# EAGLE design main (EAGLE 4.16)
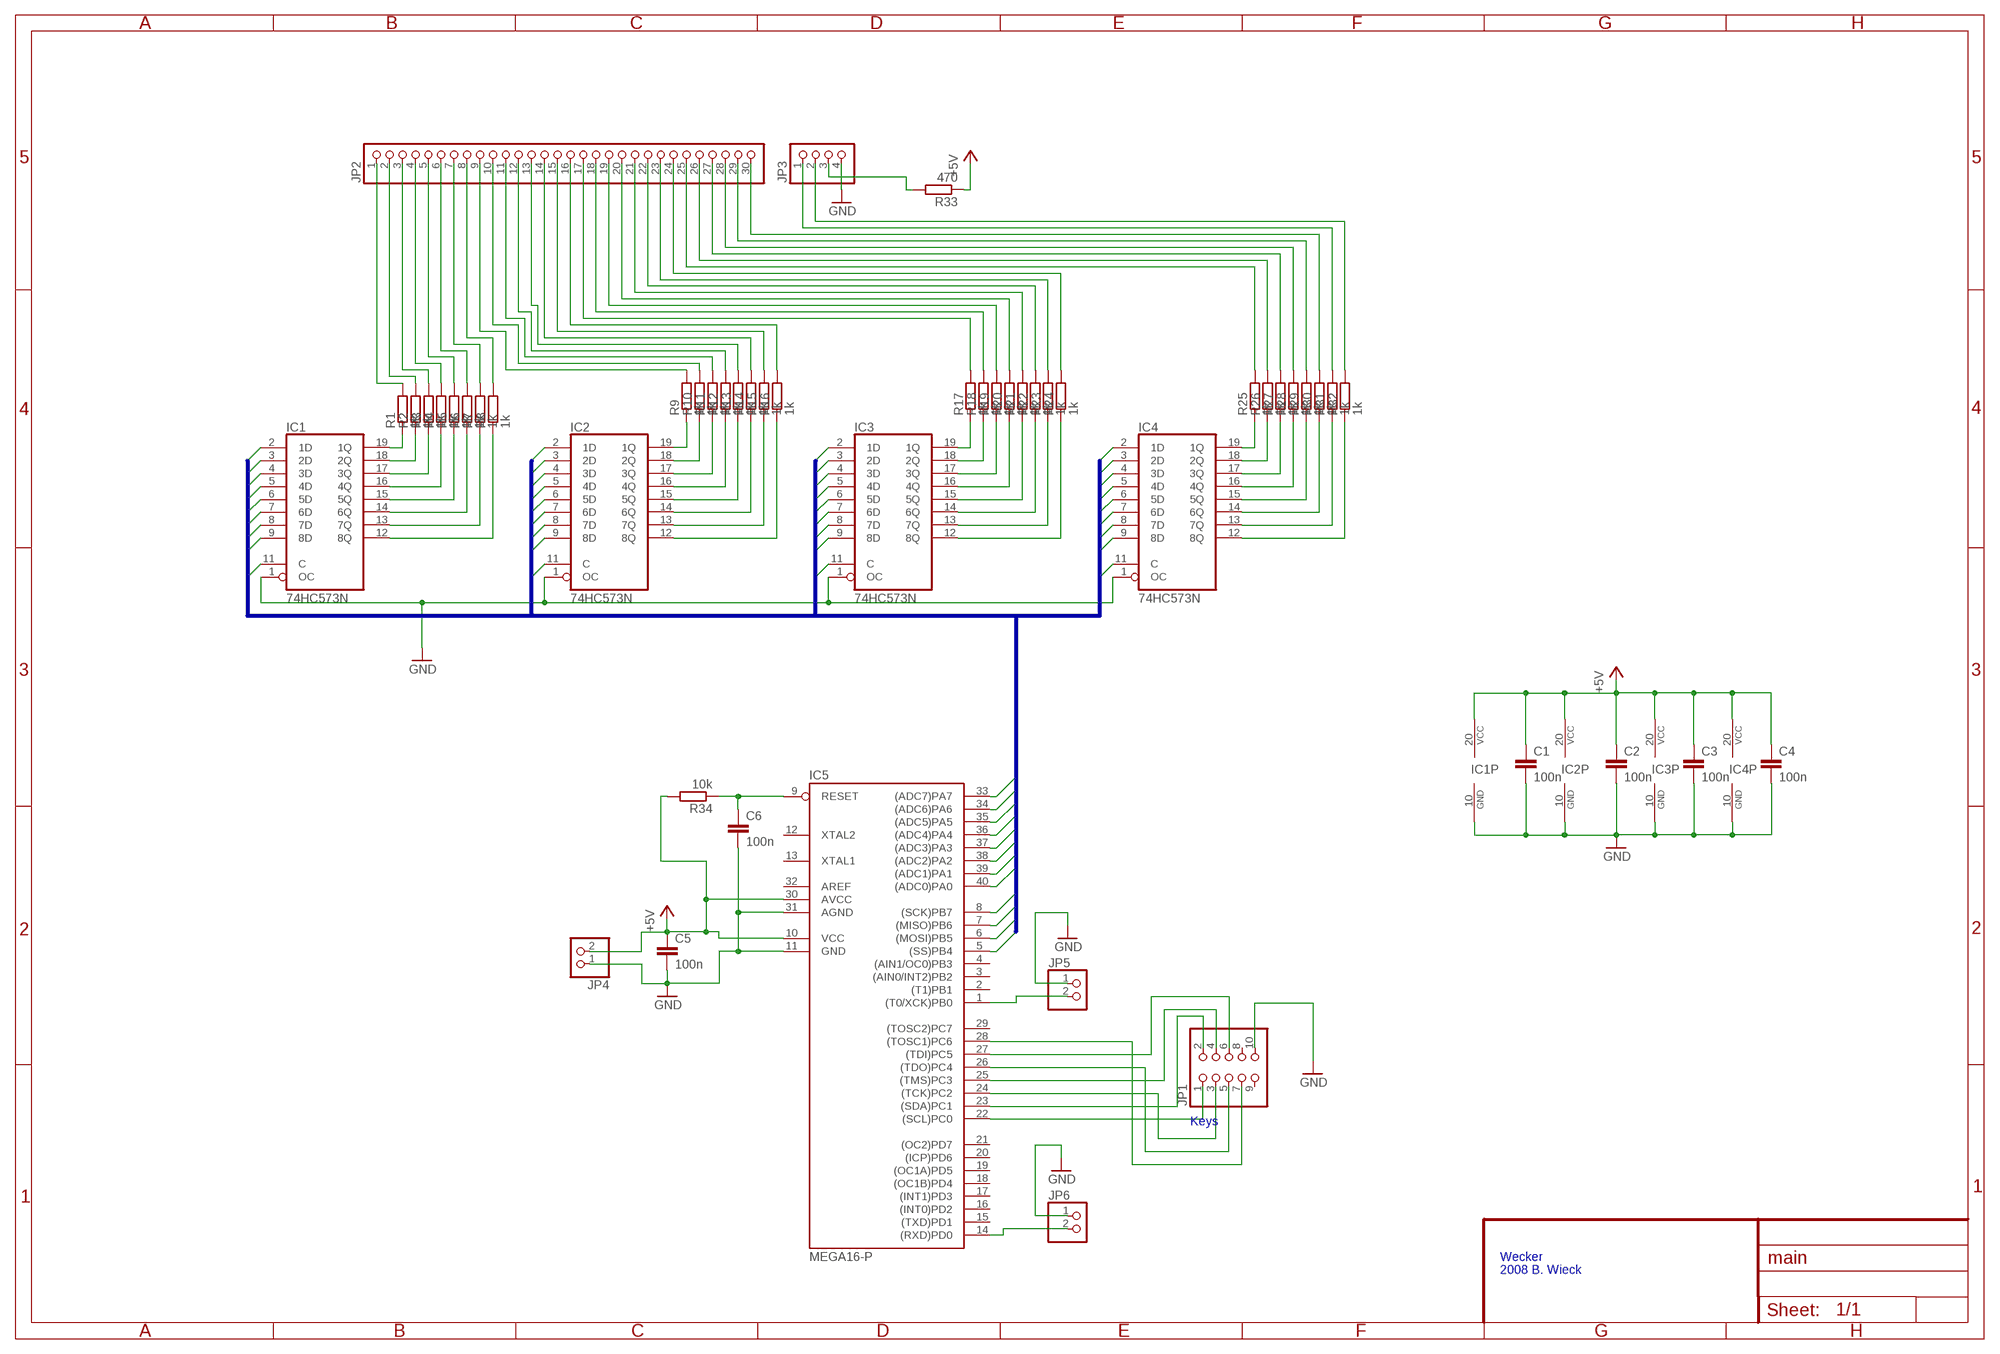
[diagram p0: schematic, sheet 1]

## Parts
C1  100n  C-EU050-024X044  [C050-024X044]
C2  100n  C-EU050-024X044  [C050-024X044]
C3  100n  C-EU050-024X044  [C050-024X044]
C4  100n  C-EU050-024X044  [C050-024X044]
C5  100n  C-EU050-024X044  [C050-024X044]
C6  100n  C-EU050-024X044  [C050-024X044]
IC1  74HC573N  [DIL20]
IC2  74HC573N  [DIL20]
IC3  74HC573N  [DIL20]
IC4  74HC573N  [DIL20]
IC5  MEGA16-P  [DIL40]
JP1  PINHD-2X5  [2X05]
JP2  PINHD-1X30  [1X30]
JP3  PINHD-1X4  [1X04]
JP4  PINHD-1X2  [1X02]
JP5  PINHD-1X2  [1X02]
JP6  PINHD-1X2  [1X02]
R1  1k  R-EU_0207/2V  [0207/2V]
R2  1k  R-EU_0207/2V  [0207/2V]
R3  1k  R-EU_0207/2V  [0207/2V]
R4  1k  R-EU_0207/2V  [0207/2V]
R5  1k  R-EU_0207/2V  [0207/2V]
R6  1k  R-EU_0207/2V  [0207/2V]
R7  1k  R-EU_0207/2V  [0207/2V]
R8  1k  R-EU_0207/2V  [0207/2V]
R9  1k  R-EU_0207/2V  [0207/2V]
R10  1k  R-EU_0207/2V  [0207/2V]
R11  1k  R-EU_0207/2V  [0207/2V]
R12  1k  R-EU_0207/2V  [0207/2V]
R13  1k  R-EU_0207/2V  [0207/2V]
R14  1k  R-EU_0207/2V  [0207/2V]
R15  1k  R-EU_0207/2V  [0207/2V]
R16  1k  R-EU_0207/2V  [0207/2V]
R17  1k  R-EU_0207/2V  [0207/2V]
R18  1k  R-EU_0207/2V  [0207/2V]
R19  1k  R-EU_0207/2V  [0207/2V]
R20  1k  R-EU_0207/2V  [0207/2V]
R21  1k  R-EU_0207/2V  [0207/2V]
R22  1k  R-EU_0207/2V  [0207/2V]
R23  1k  R-EU_0207/2V  [0207/2V]
R24  1k  R-EU_0207/2V  [0207/2V]
R25  1k  R-EU_0207/2V  [0207/2V]
R26  1k  R-EU_0207/2V  [0207/2V]
R27  1k  R-EU_0207/2V  [0207/2V]
R28  1k  R-EU_0207/2V  [0207/2V]
R29  1k  R-EU_0207/2V  [0207/2V]
R30  1k  R-EU_0207/2V  [0207/2V]
R31  1k  R-EU_0207/2V  [0207/2V]
R32  1k  R-EU_0207/2V  [0207/2V]
R33  470  R-EU_0207/2V  [0207/2V]
R34  10k  R-EU_0207/10  [0207/10]

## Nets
+5V: C1.1 C2.1 C3.1 C4.1 C5.1 IC1.20(VCC) IC2.20(VCC) IC3.20(VCC) IC4.20(VCC) IC5.10(VCC) IC5.30(AVCC) JP4.2 R33.1 R34.2
DB0: IC1.2(1D) IC2.2(1D) IC3.2(1D) IC4.2(1D) IC5.40((ADC0)PA0)
DB1: IC1.3(2D) IC2.3(2D) IC3.3(2D) IC4.3(2D) IC5.39((ADC1)PA1)
DB2: IC1.4(3D) IC2.4(3D) IC3.4(3D) IC4.4(3D) IC5.38((ADC2)PA2)
DB3: IC1.5(4D) IC2.5(4D) IC3.5(4D) IC4.5(4D) IC5.37((ADC3)PA3)
DB4: IC1.6(5D) IC2.6(5D) IC3.6(5D) IC4.6(5D) IC5.36((ADC4)PA4)
DB5: IC1.7(6D) IC2.7(6D) IC3.7(6D) IC4.7(6D) IC5.35((ADC5)PA5)
DB6: IC1.8(7D) IC2.8(7D) IC3.8(7D) IC4.8(7D) IC5.34((ADC6)PA6)
DB7: IC1.9(8D) IC2.9(8D) IC3.9(8D) IC4.9(8D) IC5.33((ADC7)PA7)
EN1: IC1.11(C) IC5.8((SCK)PB7)
EN2: IC2.11(C) IC5.7((MISO)PB6)
EN3: IC3.11(C) IC5.6((MOSI)PB5)
EN4: IC4.11(C) IC5.5((SS)PB4)
GND: C1.2 C2.2 C3.2 C4.2 C5.2 C6.2 IC1.1(OC) IC1.10(GND) IC2.1(OC) IC2.10(GND) IC3.1(OC) IC3.10(GND) IC4.1(OC) IC4.10(GND) IC5.11(GND) IC5.31(AGND) JP1.10 JP3.4 JP4.1 JP5.1 JP6.1
N$1: IC1.12(8Q) R8.1
N$2: IC2.12(8Q) R16.1
N$3: IC3.12(8Q) R24.1
N$4: IC4.12(8Q) R32.1
N$5: JP2.1 R1.2
N$6: JP2.2 R2.2
N$7: JP2.3 R3.2
N$8: JP2.4 R4.2
N$9: JP2.5 R5.2
N$10: JP2.6 R6.2
N$11: JP2.7 R7.2
N$12: JP2.8 R8.2
N$13: JP2.9 R9.2
N$14: IC1.19(1Q) R1.1
N$15: IC1.18(2Q) R2.1
N$16: IC1.17(3Q) R3.1
N$17: IC1.16(4Q) R4.1
N$18: IC1.15(5Q) R5.1
N$19: IC1.14(6Q) R6.1
N$20: IC1.13(7Q) R7.1
N$21: JP2.10 R10.2
N$22: JP2.11 R11.2
N$23: JP2.12 R12.2
N$24: JP2.13 R13.2
N$25: IC2.19(1Q) R9.1
N$26: IC2.18(2Q) R10.1
N$27: IC2.17(3Q) R11.1
N$28: IC2.16(4Q) R12.1
N$29: IC2.15(5Q) R13.1
N$30: IC2.14(6Q) R14.1
N$31: IC2.13(7Q) R15.1
N$32: JP2.14 R14.2
N$33: JP2.15 R15.2
N$34: JP2.16 R16.2
N$35: JP2.17 R17.2
N$36: JP2.18 R18.2
N$37: JP2.19 R19.2
N$38: JP2.20 R20.2
N$39: JP2.21 R21.2
N$40: IC3.19(1Q) R17.1
N$41: IC3.18(2Q) R18.1
N$42: IC3.17(3Q) R19.1
N$43: IC3.16(4Q) R20.1
N$44: IC3.15(5Q) R21.1
N$45: IC3.14(6Q) R22.1
N$46: IC3.13(7Q) R23.1
N$47: JP2.22 R22.2
N$48: JP2.23 R23.2
N$49: JP2.24 R24.2
N$50: JP2.25 R25.2
N$51: JP2.26 R26.2
N$52: JP2.27 R27.2
N$53: JP2.28 R28.2
N$54: JP2.29 R29.2
N$55: JP2.30 R30.2
N$56: IC4.19(1Q) R25.1
N$57: IC4.18(2Q) R26.1
N$58: IC4.17(3Q) R27.1
N$59: IC4.16(4Q) R28.1
N$60: IC4.15(5Q) R29.1
N$61: IC4.14(6Q) R30.1
N$62: IC4.13(7Q) R31.1
N$63: JP3.1 R31.2
N$64: JP3.2 R32.2
N$65: JP3.3 R33.2
N$67: C6.1 IC5.9(RESET) R34.1
N$68: IC5.26((TDO)PC4) JP1.5
N$69: IC5.22((SCL)PC0) JP1.1
N$70: IC5.23((SDA)PC1) JP1.2
N$71: IC5.24((TCK)PC2) JP1.3
N$72: IC5.25((TMS)PC3) JP1.4
N$73: IC5.27((TDI)PC5) JP1.6
N$74: IC5.28((TOSC1)PC6) JP1.7
N$77: IC5.1((T0/XCK)PB0) JP5.2
N$78: IC5.14((RXD)PD0) JP6.2
Unconnected: IC5.2((T1)PB1) IC5.3((AIN0/INT2)PB2) IC5.4((AIN1/OC0)PB3) IC5.12(XTAL2) IC5.13(XTAL1) IC5.15((TXD)PD1) IC5.16((INT0)PD2) IC5.17((INT1)PD3) IC5.18((OC1B)PD4) IC5.19((OC1A)PD5) IC5.20((ICP)PD6) IC5.21((OC2)PD7) IC5.29((TOSC2)PC7) JP1.8 JP1.9

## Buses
DATA:DB[0..7],EN[1..4]

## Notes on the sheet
- Keys
- Wecker
- 2008 B. Wieck

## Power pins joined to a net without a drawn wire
AREF: IC5.32(AREF)

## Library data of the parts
C1-C6 = rcl:C-EU: CAPACITOR, European symbol
IC1-IC4 = 74xx-us:74*573: 8-bit D latch BUS DRIVER
IC5 = atmel:MEGA16-P: MICROCONTROLLER 16 Kbytes FLASH 1 kbytes SRAM 512 bytes EEPROM USART 8-channel 10 bit ADC Source: avr.lbr
JP1 = pinhead:PINHD-2X5: PIN HEADER
JP2 = pinhead:PINHD-1X30: PIN HEADER
JP3 = pinhead:PINHD-1X4: PIN HEADER
JP4-JP6 = pinhead:PINHD-1X2: PIN HEADER
R1-R34 = rcl:R-EU_: RESISTOR, European symbol

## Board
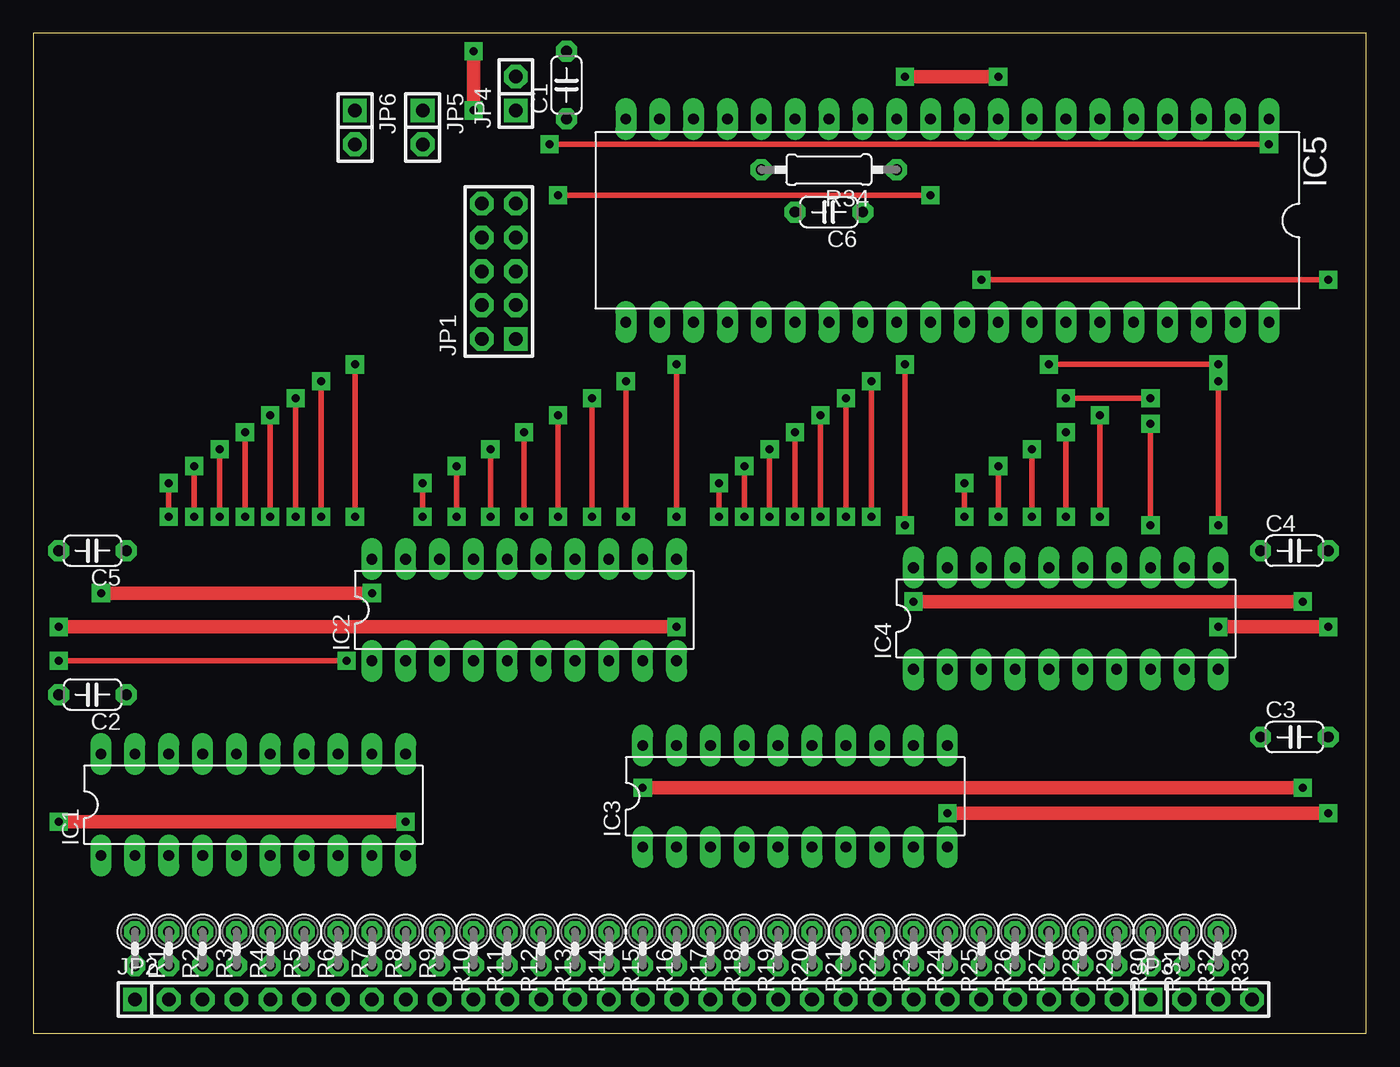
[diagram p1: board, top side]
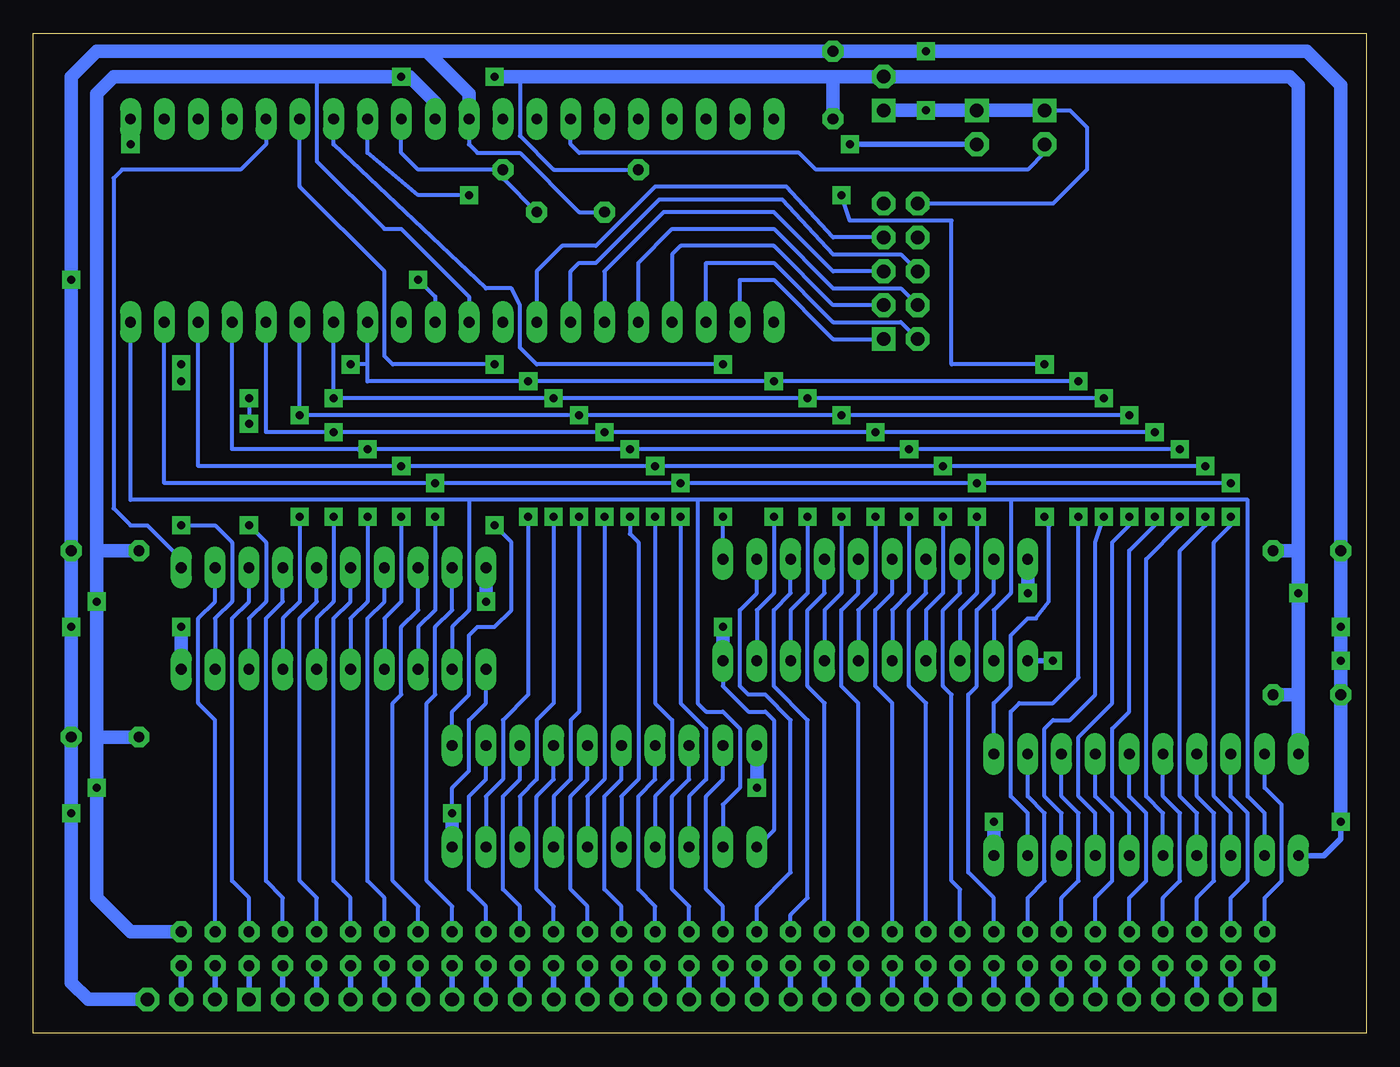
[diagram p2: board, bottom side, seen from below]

Size 100 x 75 mm. Coordinates in mm from the lower left corner, seen from the top.
Outline: 0,0 100,0 100,75 0,75 0,0
Copper layers (1*16): Top 0.035mm / dielectric 1.5mm / Bottom 0.035mm
Design rules "BWieck": minimum track width 12mil, minimum drill 24mil, track to track 12mil, track to pad 12mil, pad to pad 10mil, via to via 12mil, smd to smd 8mil, copper to edge 40mil, drill to drill 8mil, minimum pad ring 15mil, minimum via ring 15mil, stop-mask expansion 4mil, vias tented up to drill 0mil, thermal gap 10mil

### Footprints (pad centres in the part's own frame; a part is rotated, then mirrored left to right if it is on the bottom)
C050-024X044 = drill 0.813 octagon: 1 -2.54,0; 2 2.54,0
DIL20 = drill 0.813 long: 1 -11.43,-3.81; 2 -8.89,-3.81; 3 -6.35,-3.81; 4 -3.81,-3.81; 5 -1.27,-3.81; 6 1.27,-3.81; 7 3.81,-3.81; 8 6.35,-3.81; 9 8.89,-3.81; 10 11.43,-3.81; 11 11.43,3.81; 12 8.89,3.81; 13 6.35,3.81; 14 3.81,3.81; 15 1.27,3.81; 16 -1.27,3.81; 17 -3.81,3.81; 18 -6.35,3.81; 19 -8.89,3.81; 20 -11.43,3.81
DIL40 = drill 0.813 long: 1 -24.13,-7.62; 2 -21.59,-7.62; 3 -19.05,-7.62; 4 -16.51,-7.62; 5 -13.97,-7.62; 6 -11.43,-7.62; 7 -8.89,-7.62; 8 -6.35,-7.62; 9 -3.81,-7.62; 10 -1.27,-7.62; 11 1.27,-7.62; 12 3.81,-7.62; 13 6.35,-7.62; 14 8.89,-7.62; 15 11.43,-7.62; 16 13.97,-7.62; 17 16.51,-7.62; 18 19.05,-7.62; 19 21.59,-7.62; 20 24.13,-7.62; 21 24.13,7.62; 22 21.59,7.62; 23 19.05,7.62; 24 16.51,7.62; 25 13.97,7.62; 26 11.43,7.62; 27 8.89,7.62; 28 6.35,7.62; 29 3.81,7.62; 30 1.27,7.62; 31 -1.27,7.62; 32 -3.81,7.62; 33 -6.35,7.62; 34 -8.89,7.62; 35 -11.43,7.62; 36 -13.97,7.62; 37 -16.51,7.62; 38 -19.05,7.62; 39 -21.59,7.62; 40 -24.13,7.62
2X05 = drill 1.016 square: 1 -5.08,-1.27 | drill 1.016 octagon: 2 -5.08,1.27; 3 -2.54,-1.27; 4 -2.54,1.27; 5 0,-1.27; 6 0,1.27; 7 2.54,-1.27; 8 2.54,1.27; 9 5.08,-1.27; 10 5.08,1.27
1X30 = drill 1.016 square: 1 -36.83,0 | drill 1.016 octagon: 2 -34.29,0; 3 -31.75,0; 4 -29.21,0; 5 -26.67,0; 6 -24.13,0; 7 -21.59,0; 8 -19.05,0; 9 -16.51,0; 10 -13.97,0; 11 -11.43,0; 12 -8.89,0; 13 -6.35,0; 14 -3.81,0; 15 -1.27,0; 16 1.27,0; 17 3.81,0; 18 6.35,0; 19 8.89,0; 20 11.43,0; 21 13.97,0; 22 16.51,0; 23 19.05,0; 24 21.59,0; 25 24.13,0; 26 26.67,0; 27 29.21,0; 28 31.75,0; 29 34.29,0; 30 36.83,0
1X04 = drill 1.016 square: 1 -3.81,0 | drill 1.016 octagon: 2 -1.27,0; 3 1.27,0; 4 3.81,0
1X02 = drill 1.016 square: 1 -1.27,0 | drill 1.016 octagon: 2 1.27,0
0207/2V = drill 0.813 octagon: 1 -1.27,0; 2 1.27,0
0207/10 = drill 0.813 octagon: 1 -5.08,0; 2 5.08,0

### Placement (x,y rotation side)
C1  40.01,71.12 90 top
C2  4.45,25.4 180 top
C3  94.61,22.23 0 top
C4  94.61,36.2 0 top
C5  4.45,36.2 180 top
C6  59.69,61.59 180 top
IC1  16.51,17.14 0 top
IC2  36.83,31.75 0 top
IC3  57.15,17.78 0 top
IC4  77.47,31.11 0 top
IC5  68.58,60.96 180 top
JP1  34.92,57.15 90 top
JP2  44.45,2.54 0 top
JP3  87.63,2.54 0 top
JP4  36.2,70.48 90 top
JP5  29.21,67.94 270 top
JP6  24.13,67.94 270 top
R1  7.62,6.35 270 top
R2  10.16,6.35 270 top
R3  12.7,6.35 270 top
R4  15.24,6.35 270 top
R5  17.78,6.35 270 top
R6  20.32,6.35 270 top
R7  22.86,6.35 270 top
R8  25.4,6.35 270 top
R9  27.94,6.35 270 top
R10  30.48,6.35 270 top
R11  33.02,6.35 270 top
R12  35.56,6.35 270 top
R13  38.1,6.35 270 top
R14  40.64,6.35 270 top
R15  43.18,6.35 270 top
R16  45.72,6.35 270 top
R17  48.26,6.35 270 top
R18  50.8,6.35 270 top
R19  53.34,6.35 270 top
R20  55.88,6.35 270 top
R21  58.42,6.35 270 top
R22  60.96,6.35 270 top
R23  63.5,6.35 270 top
R24  66.04,6.35 270 top
R25  68.58,6.35 270 top
R26  71.12,6.35 270 top
R27  73.66,6.35 270 top
R28  76.2,6.35 270 top
R29  78.74,6.35 270 top
R30  81.28,6.35 270 top
R31  83.82,6.35 270 top
R32  86.36,6.35 270 top
R33  88.9,6.35 270 top
R34  59.69,64.77 180 top

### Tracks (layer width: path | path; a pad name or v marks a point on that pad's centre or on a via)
+5V  (via drill 0.6)
  Top 1.016: v95.25,32.38 v66.04,32.38 | v95.25,18.41 v45.72,18.41 | v65.41,71.75 v72.39,71.75 | v5.08,33.02 v25.4,33.02
  Bottom 0.305: R34.2 60.96,64.77 63.5,67.31 63.5,71.75 | IC5.30 67.31,55.24 72.39,60.33 73.66,60.33 78.74,65.41 78.74,71.75
  Bottom 1.016: IC5.10 69.85,69.85 71.75,71.75 v72.39,71.75 78.74,71.75 93.98,71.75 95.25,70.48 95.25,36.2 | 95.25,36.2 v95.25,32.38 95.25,22.23 | v66.04,32.38 IC4.20 | v45.72,18.41 IC3.20 | 95.25,22.23 v95.25,18.41 95.25,10.16 92.71,7.62 R33.1 | IC1.20 5.08,25.4 | 5.08,25.4 v5.08,33.02 5.08,36.2 | 5.08,36.2 5.08,71.12 5.71,71.75 JP4.2 40.01,71.75 | 40.01,71.75 63.5,71.75 v65.41,71.75 | 5.08,25.4 C2.1 | 95.25,22.23 C3.1 | 95.25,36.2 C4.1 | 40.01,71.75 C1.1 | v25.4,33.02 IC2.20 | 5.08,36.2 C5.1
DB0
  Bottom 0.305: IC1.2 7.62,16.51 8.89,17.78 8.89,40.01 26.67,40.01 | 26.67,40.01 50.16,40.01 | 50.16,40.01 67.31,40.01 | 67.31,40.01 92.71,40.01 IC5.40 | IC2.2 27.94,31.75 26.67,33.02 26.67,40.01 | IC3.2 48.26,17.14 46.99,18.41 46.99,22.86 48.26,24.13 49.53,24.13 50.16,24.77 50.16,40.01 | IC4.2 68.58,30.48 67.31,31.75 67.31,40.01
DB1  (via drill 0.6)
  Top 0.406: v10.16,38.73 v10.16,41.27 | v29.21,41.27 v29.21,38.73 | v51.44,41.27 v51.44,38.73 | v69.85,41.27 v69.85,38.73
  Bottom 0.305: IC5.39 90.17,41.27 v69.85,41.27 v51.44,41.27 v29.21,41.27 v10.16,41.27 | IC1.3 10.16,16.51 11.43,17.78 11.43,36.83 10.16,38.1 v10.16,38.73 | IC2.3 30.48,31.75 29.21,33.02 v29.21,38.73 | IC3.3 50.8,17.78 49.53,19.05 49.53,22.86 51.44,24.77 v51.44,38.73 | IC4.3 71.12,30.48 69.85,31.75 v69.85,38.73
DB2  (via drill 0.6)
  Top 0.406: v12.06,38.73 v12.06,42.55 | v31.75,42.55 v31.75,38.73 | v53.34,42.55 v53.34,38.73 | v72.39,42.55 v72.39,38.73
  Bottom 0.305: IC5.38 87.63,42.55 v72.39,42.55 v53.34,42.55 v31.75,42.55 v12.06,42.55 | IC1.4 12.7,16.51 13.97,17.78 13.97,36.2 12.06,38.1 v12.06,38.73 | IC2.4 33.02,31.75 31.75,33.02 v31.75,38.73 | IC3.4 53.34,17.78 52.07,19.05 52.07,23.5 53.34,24.77 v53.34,38.73 | IC4.4 73.66,31.11 72.39,32.38 v72.39,38.73
DB3  (via drill 0.6)
  Top 0.406: v13.97,38.73 v13.97,43.81 | v34.29,43.81 v34.29,38.73 | v55.24,43.81 v55.24,38.73 | v74.93,43.81 v74.93,38.73
  Bottom 0.305: IC5.37 85.09,43.81 75.56,43.81 | IC1.5 15.24,16.51 16.51,17.78 16.51,35.56 13.97,38.1 | v13.97,43.81 v34.29,43.81 v55.24,43.81 v74.93,43.81 | IC2.5 35.56,31.75 34.29,33.02 v34.29,38.73 | IC3.5 55.88,17.78 54.61,19.05 54.61,36.83 55.24,37.47 v55.24,38.73 | IC4.5 76.2,31.11 74.93,32.38 v74.93,38.73
  Bottom 0.406: 13.97,38.1 v13.97,38.73 | v74.93,43.81 75.56,43.81
DB4  (via drill 0.6)
  Top 0.406: v15.88,38.73 v15.88,45.09 | v36.83,45.09 v36.83,38.73 | v57.15,45.09 v57.15,38.73 | v77.47,45.09 v77.47,38.73
  Bottom 0.305: IC5.36 82.55,45.09 v77.47,45.09 v57.15,45.09 v36.83,45.09 v15.88,45.09 | IC1.6 17.78,16.51 19.05,17.78 19.05,22.86 17.78,24.13 17.78,36.2 15.88,38.1 v15.88,38.73 | IC2.6 38.1,31.75 36.83,33.02 v36.83,38.73 | IC3.6 58.42,17.78 57.15,19.05 v57.15,38.73 | IC4.6 78.74,31.11 77.47,32.38 v77.47,38.73
DB5  (via drill 0.6)
  Top 0.406: v17.78,38.73 v17.78,46.35 | v39.37,46.35 v39.37,38.73 | v59.05,46.35 v59.05,38.73 | v80.01,46.35 v80.01,38.73
  Bottom 0.305: IC1.7 20.32,16.51 21.59,17.78 21.59,22.23 19.05,24.77 19.05,36.83 17.78,38.1 v17.78,38.73 | v17.78,46.35 v39.37,46.35 v59.05,46.35 v80.01,46.35 IC5.35 | IC2.7 40.64,31.75 39.37,33.02 v39.37,38.73 | IC3.7 60.96,17.78 59.69,19.05 59.69,23.5 59.05,24.13 v59.05,38.73 | IC4.7 81.28,31.11 80.01,32.38 v80.01,38.73
DB6  (via drill 0.6)
  Top 0.406: v19.68,38.73 v19.68,47.62 | v41.91,47.62 v41.91,38.73 | v60.96,47.62 v60.96,38.73 | v83.82,45.72 v83.82,38.1 | v77.47,47.62 v83.82,47.62
  Bottom 0.305: IC5.34 v77.47,47.62 v60.96,47.62 v41.91,47.62 v19.68,47.62 | IC1.8 22.86,16.51 24.13,17.78 24.13,22.86 23.5,23.5 22.23,23.5 20.32,25.4 20.32,36.83 v19.68,38.73 | IC2.8 43.18,31.75 41.91,33.02 v41.91,38.73 | IC3.8 63.5,17.78 62.23,19.05 62.23,23.5 60.96,24.77 v60.96,38.73 | IC4.8 83.82,31.11 82.55,32.38 82.55,36.83 v83.82,38.1 | v83.82,47.62 v83.82,45.72
DB7  (via drill 0.6)
  Top 0.406: v21.59,38.73 v21.59,48.9 | v44.45,48.9 v44.45,38.73 | v62.87,48.9 v62.87,38.73 | v88.9,48.9 v88.9,38.1 | v76.2,50.16 v88.9,50.16
  Bottom 0.305: 74.93,50.16 74.93,48.9 v62.87,48.9 v44.45,48.9 v21.59,48.9 | 74.93,50.16 IC5.33 | IC1.9 25.4,16.51 26.67,17.78 26.67,24.13 26.04,24.77 23.5,24.77 21.59,26.67 v21.59,38.73 | IC2.9 45.72,31.75 44.45,33.02 v44.45,38.73 | IC3.9 66.04,17.78 64.77,19.05 64.77,23.5 62.87,25.4 v62.87,38.73 | IC4.9 86.36,31.11 85.09,32.38 85.09,36.83 86.36,38.1 v88.9,38.1 | 74.93,50.16 v76.2,50.16
  Bottom 0.406: v88.9,50.16 v88.9,48.9
EN1  (via drill 0.6)
  Top 0.406: v24.13,38.73 v24.13,50.16 | v39.37,62.87 v67.31,62.87
  Bottom 0.305: IC1.11 27.94,24.77 26.67,26.04 26.67,29.84 25.4,31.11 24.77,31.11 23.81,32.38 23.81,38.1 | v24.13,50.16 31.11,50.16 31.11,60.96 38.73,60.96 v39.37,62.87 | v67.31,62.87 71.12,62.87 74.93,66.04 IC5.8
  Bottom 0.406: 23.81,38.1 v24.13,38.73
EN2  (via drill 0.6)
  Top 0.406: v48.26,38.73 v48.26,50.16
  Bottom 0.305: IC2.11 v48.26,38.73 | v48.26,50.16 62.23,50.16 63.5,51.44 63.5,54.61 64.14,55.88 66.04,55.88 77.47,66.67 IC5.7
EN3  (via drill 0.6)
  Top 0.406: v65.41,38.1 v65.41,50.16
  Bottom 0.305: IC3.11 68.58,24.13 67.31,25.4 67.31,29.84 66.67,30.48 65.41,30.48 64.14,31.75 64.14,36.83 v65.41,38.1 | v65.41,50.16 73.03,50.16 73.66,50.8 73.66,57.15 80.01,63.5 IC5.6
EN4
  Bottom 0.305: IC5.5 82.55,66.67 84.45,64.77 93.34,64.77 93.98,64.14 93.98,39.37 92.71,38.1 91.44,38.1 88.9,35.56 IC4.11
GND  (via drill 0.6)
  Top 0.406: v1.91,27.94 v23.5,27.94 | v97.16,56.52 v71.12,56.52
  Top 1.016: v97.16,30.48 v88.9,30.48 | v97.16,16.51 v68.58,16.51 | v1.91,15.88 v27.94,15.88 | v33.02,73.66 v33.02,69.22 | v1.91,30.48 v48.26,30.48
  Bottom 0.305: C6.2 59.05,61.59 63.5,66.04 66.67,66.04 67.31,66.67 IC5.11 | IC4.1 66.04,24.77 67.31,23.5 67.31,19.68 68.58,18.41 v68.58,16.51 | IC2.10 48.26,26.04 46.35,24.13 45.09,24.13 44.45,23.5 44.45,15.24 IC3.1 | JP1.10 23.5,62.23 20.95,64.77 20.95,67.94 22.23,69.22 JP6.1 | IC5.31 69.85,55.24 v71.12,56.52
  Bottom 0.406: IC1.1 3.17,13.34 1.91,14.61 v1.91,15.88 | v23.5,27.94 IC2.1
  Bottom 1.016: 70.48,73.66 95.25,73.66 97.16,71.75 97.16,57.15 v97.16,56.52 C4.2 v97.16,30.48 C3.2 v97.16,16.51 97.16,3.81 95.89,2.54 JP3.4 | v88.9,30.48 IC4.10 | v68.58,16.51 IC3.10 | IC5.11 67.31,70.48 70.48,73.66 | v27.94,15.88 IC1.10 | v1.91,15.88 C2.2 v1.91,27.94 v1.91,30.48 C5.2 1.91,71.12 4.45,73.66 v33.02,73.66 C1.2 70.48,73.66 | JP4.1 v33.02,69.22 JP5.1 JP6.1 | v48.26,30.48 IC2.10
N$1
  Bottom 0.305: IC1.12 25.4,17.78 24.13,16.51 24.13,11.43 25.4,10.16 R8.1
N$2
  Bottom 0.305: IC2.12 45.72,33.02 46.99,31.75 46.99,26.04 46.35,25.4 45.09,25.4 43.18,23.5 43.18,12.06 45.72,9.53 R16.1
N$3
  Bottom 0.305: IC3.12 66.04,19.05 67.31,17.78 67.31,10.79 66.04,9.53 R24.1
N$4
  Bottom 0.305: R32.1 86.36,23.5 87.63,24.77 87.63,31.11 86.36,32.38 IC4.12
N$5
  Bottom 0.406: JP2.1 R1.2
N$6
  Bottom 0.406: JP2.2 R2.2
N$7
  Bottom 0.406: JP2.3 R3.2
N$8
  Bottom 0.406: JP2.4 R4.2
N$9
  Bottom 0.406: JP2.5 R5.2
N$10
  Bottom 0.406: JP2.6 R6.2
N$11
  Bottom 0.406: JP2.7 R7.2
N$12
  Bottom 0.406: JP2.8 R8.2
N$13
  Bottom 0.406: JP2.9 R9.2
N$14
  Bottom 0.305: IC1.19 7.62,18.41 6.35,17.14 6.35,11.43 7.62,10.16 R1.1
N$15
  Bottom 0.305: IC1.18 10.16,17.78 8.89,16.51 8.89,11.43 10.16,10.16 R2.1
N$16
  Bottom 0.305: IC1.17 12.7,17.78 11.43,16.51 11.43,11.43 12.7,10.16 R3.1
N$17
  Bottom 0.305: IC1.16 15.24,17.78 13.97,16.51 13.97,11.43 15.24,10.16 R4.1
N$18
  Bottom 0.305: IC1.15 17.78,17.78 16.51,16.51 16.51,11.43 17.78,10.16 R5.1
N$19
  Bottom 0.305: IC1.14 20.32,17.78 19.05,16.51 19.05,11.43 20.32,10.16 R6.1
N$20
  Bottom 0.305: IC1.13 22.86,17.78 21.59,16.51 21.59,11.43 22.86,10.16 R7.1
N$21
  Bottom 0.406: JP2.10 R10.2
N$22
  Bottom 0.406: JP2.11 R11.2
N$23
  Bottom 0.406: JP2.12 R12.2
N$24
  Bottom 0.406: JP2.13 R13.2
N$25
  Bottom 0.305: R9.1 27.94,10.16 29.84,12.06 29.84,25.4 29.21,26.04 29.21,31.75 27.94,33.02 IC2.19
N$26
  Bottom 0.305: R10.1 30.48,10.79 31.11,11.43 31.11,25.4 31.75,26.04 31.75,31.75 30.48,33.02 IC2.18
N$27
  Bottom 0.305: R11.1 33.02,24.77 34.29,26.04 34.29,31.75 33.02,33.02 IC2.17
N$28
  Bottom 0.305: R12.1 35.56,24.77 36.83,26.04 36.83,31.75 35.56,33.02 IC2.16
N$29
  Bottom 0.305: R13.1 38.1,24.77 39.37,26.04 39.37,31.75 38.1,33.02 IC2.15
N$30
  Bottom 0.305: R14.1 40.64,24.77 41.91,26.04 41.91,31.75 40.64,33.02 IC2.14
N$31
  Bottom 0.305: IC2.13 43.18,33.02 44.45,31.75 44.45,26.04 41.91,23.5 41.91,10.16 43.18,8.89 R15.1
N$32
  Bottom 0.406: JP2.14 R14.2
N$33
  Bottom 0.406: JP2.15 R15.2
N$34
  Bottom 0.406: JP2.16 R16.2
N$35
  Bottom 0.406: JP2.17 R17.2
N$36
  Bottom 0.406: JP2.18 R18.2
N$37
  Bottom 0.406: JP2.19 R19.2
N$38
  Bottom 0.406: JP2.20 R20.2
N$39
  Bottom 0.406: JP2.21 R21.2
N$40
  Bottom 0.305: IC3.19 48.26,19.05 49.53,17.78 49.53,10.79 48.26,9.53 R17.1
N$41
  Bottom 0.305: IC3.18 50.8,19.05 52.07,17.78 52.07,10.79 50.8,9.53 R18.1
N$42
  Bottom 0.305: IC3.17 53.34,19.05 54.61,17.78 54.61,10.79 53.34,9.53 R19.1
N$43
  Bottom 0.305: IC3.16 55.88,19.05 57.15,17.78 57.15,10.79 55.88,9.53 R20.1
N$44
  Bottom 0.305: IC3.15 58.42,19.05 59.69,17.78 59.69,10.79 58.42,9.53 R21.1
N$45
  Bottom 0.305: IC3.14 60.96,19.05 62.23,17.78 62.23,10.79 60.96,9.53 R22.1
N$46
  Bottom 0.305: IC3.13 63.5,19.05 64.77,17.78 64.77,10.79 63.5,9.53 R23.1
N$47
  Bottom 0.406: JP2.22 R22.2
N$48
  Bottom 0.406: JP2.23 R23.2
N$49
  Bottom 0.406: JP2.24 R24.2
N$50
  Bottom 0.406: JP2.25 R25.2
N$51
  Bottom 0.406: JP2.26 R26.2
N$52
  Bottom 0.406: JP2.27 R27.2
N$53
  Bottom 0.406: JP2.28 R28.2
N$54
  Bottom 0.406: JP2.29 R29.2
N$55
  Bottom 0.406: JP2.30 R30.2
N$56
  Bottom 0.305: R25.1 68.58,9.53 70.48,11.43 70.48,24.77 69.85,25.4 69.85,30.48 68.58,31.75 IC4.19
N$57
  Bottom 0.305: R26.1 71.12,9.53 73.03,11.43 73.03,24.77 72.39,25.4 72.39,30.48 71.12,31.75 IC4.18
N$58
  Bottom 0.305: R27.1 73.66,10.16 74.93,11.43 74.93,31.11 73.66,32.38 IC4.17
N$59
  Bottom 0.305: R28.1 76.2,10.16 77.47,11.43 77.47,31.11 76.2,32.38 IC4.16
N$60
  Bottom 0.305: R29.1 78.74,10.16 80.01,11.43 80.01,31.11 78.74,32.38 IC4.15
N$61
  Bottom 0.305: R30.1 81.28,10.16 82.55,11.43 82.55,31.11 81.28,32.38 IC4.14
N$62
  Bottom 0.305: R31.1 83.82,10.16 85.09,11.43 85.09,31.11 83.82,32.38 IC4.13
N$63
  Bottom 0.406: JP3.1 R31.2
N$64
  Bottom 0.406: JP3.2 R32.2
N$65
  Bottom 0.406: JP3.3 R33.2
N$67
  Bottom 0.305: R34.1 71.12,64.77 72.39,66.04 IC5.9 | 64.77,64.14 C6.1
  Bottom 0.406: R34.1 64.77,64.14
N$68
  Bottom 0.305: JP1.5 40.01,57.15 44.45,61.59 52.7,61.59 57.15,57.15 IC5.26
N$69
  Bottom 0.305: IC5.22 46.99,56.52 44.45,56.52 40.01,52.07 JP1.1
N$70
  Bottom 0.305: IC5.23 49.53,57.78 44.45,57.78 40.01,53.34 34.92,53.34 JP1.2
N$71
  Bottom 0.305: JP1.3 40.01,54.61 44.45,59.05 51.44,59.05 52.07,58.42 IC5.24
N$72
  Bottom 0.305: IC5.25 54.61,57.78 52.07,60.33 44.45,60.33 40.01,55.88 34.92,55.88 JP1.4
N$73
  Bottom 0.305: IC5.27 59.69,57.15 59.05,57.78 57.78,57.78 53.02,62.55 43.81,62.55 40.01,58.42 34.92,58.42 JP1.6
N$74
  Bottom 0.305: JP1.7 40.01,59.69 43.5,63.5 53.34,63.5 57.78,59.05 60.33,59.05 62.23,57.15 IC5.28
N$77  (via drill 0.6)
  Top 0.406: v38.73,66.67 v92.71,66.67
  Bottom 0.406: JP5.2 v38.73,66.67 | v92.71,66.67 IC5.1
N$78
  Bottom 0.305: 24.13,66.04 25.4,64.77 41.27,64.77 42.55,66.04 59.05,66.04 59.69,66.67 IC5.14
  Bottom 0.406: JP6.2 24.13,66.04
